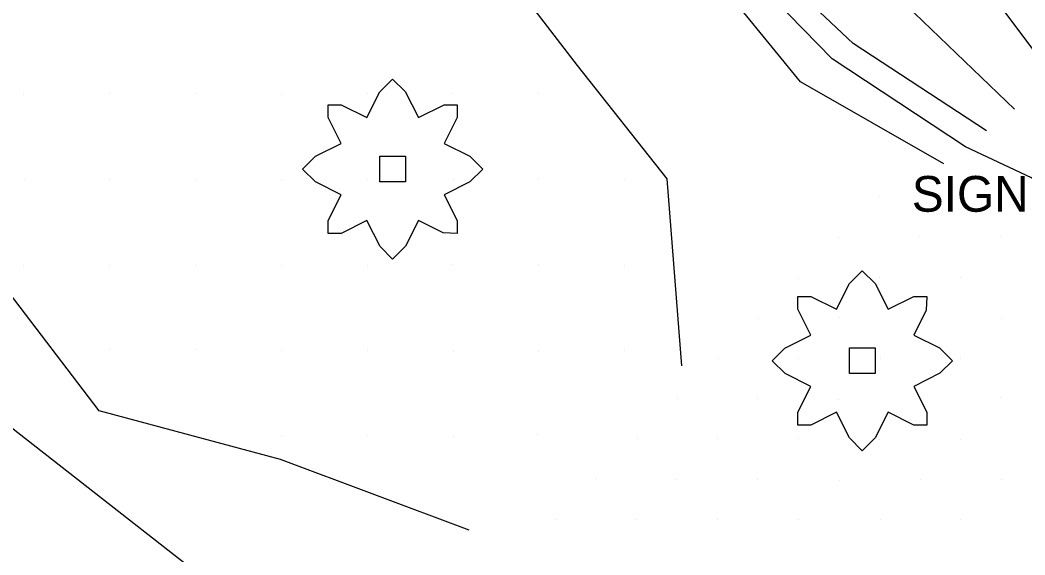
# Model space of a CAD drawing. Extents: x 1602514 to 1609837, y 863887 to 871157.
# Drawn here: x 1605247.7 to 1605423.3, y 867056.2 to 867149.8 of the extents above; entities that cross this region are included whole.
import ezdxf

# ---------------------------------------------------------------- set-up
doc = ezdxf.new("R2010")
doc.units = 0
for name, color, linetype in [('Environmental-New trees', 7, 'Continuous'), ('Roadway-Signs', 7, 'Continuous'), ('Survey-Ditches', 7, 'Continuous'), ('Survey-Entrances', 7, 'Continuous'), ('Survey-Flow line', 7, 'Continuous'), ('Survey-Ridge Lines', 7, 'Continuous'), ('Survey-Shoulders', 7, 'Continuous'), ('Survey-Spot dirt', 7, 'Continuous')]:
    doc.layers.add(name, color=color, linetype=linetype)

msp = doc.modelspace()

# ---------------------------------------------------------------- linework, layer by layer
at = {"layer": 'Environmental-New trees'}
for points in [[(1605301.57, 867134.94), (1605303.82, 867134.94), (1605308.32, 867132.69), (1605310.57, 867137.19), (1605312.82, 867139.44), (1605315.02, 867137.25), (1605317.32, 867132.69), (1605321.83, 867134.94), (1605324.08, 867134.94), (1605324.08, 867132.69), (1605321.83, 867128.19), (1605326.33, 867125.94), (1605328.58, 867123.69), (1605326.33, 867121.44), (1605321.83, 867119.19), (1605324.08, 867114.69), (1605324.08, 867112.44), (1605321.65, 867112.52), (1605317.32, 867114.69), (1605315.07, 867110.19), (1605312.82, 867107.94), (1605310.63, 867110.13), (1605308.32, 867114.69), (1605303.82, 867112.44), (1605301.57, 867112.44), (1605301.57, 867114.69), (1605303.82, 867119.19), (1605299.32, 867121.44), (1605297.07, 867123.69), (1605299.32, 867125.94), (1605303.82, 867128.19), (1605301.57, 867132.69)], [(1605301.57, 867134.94), (1605303.82, 867134.94), (1605308.32, 867132.69), (1605310.57, 867137.19), (1605312.82, 867139.44), (1605315.02, 867137.25), (1605317.32, 867132.69), (1605321.83, 867134.94), (1605324.08, 867134.94), (1605324.08, 867132.69), (1605321.83, 867128.19), (1605326.33, 867125.94), (1605328.58, 867123.69), (1605326.33, 867121.44), (1605321.83, 867119.19), (1605324.08, 867114.69), (1605324.08, 867112.44), (1605321.65, 867112.52), (1605317.32, 867114.69), (1605315.07, 867110.19), (1605312.82, 867107.94), (1605310.63, 867110.13), (1605308.32, 867114.69), (1605303.82, 867112.44), (1605301.57, 867112.44), (1605301.57, 867114.69), (1605303.82, 867119.19), (1605299.32, 867121.44), (1605297.07, 867123.69), (1605299.32, 867125.94), (1605303.82, 867128.19), (1605301.57, 867132.69)], [(1605315.07, 867125.94), (1605315.07, 867121.44), (1605310.57, 867121.44), (1605310.57, 867125.94)], [(1605315.07, 867125.94), (1605315.07, 867121.44), (1605310.57, 867121.44), (1605310.57, 867125.94)], [(1605383.66, 867078.91), (1605383.66, 867081.16), (1605385.91, 867085.66), (1605381.41, 867087.91), (1605379.16, 867090.16), (1605381.35, 867092.35), (1605385.91, 867094.66), (1605383.66, 867099.16), (1605383.66, 867101.41), (1605385.91, 867101.41), (1605390.41, 867099.16), (1605392.66, 867103.66), (1605394.91, 867105.91), (1605397.17, 867103.66), (1605399.42, 867099.16), (1605403.92, 867101.41), (1605406.17, 867101.41), (1605406.08, 867098.99), (1605403.92, 867094.66), (1605408.42, 867092.41), (1605410.67, 867090.16), (1605408.48, 867087.97), (1605403.92, 867085.66), (1605406.17, 867081.16), (1605406.17, 867078.91), (1605403.92, 867078.91), (1605399.42, 867081.16), (1605397.17, 867076.66), (1605394.91, 867074.41), (1605392.66, 867076.66), (1605390.41, 867081.16), (1605385.91, 867078.91)], [(1605383.66, 867078.91), (1605383.66, 867081.16), (1605385.91, 867085.66), (1605381.41, 867087.91), (1605379.16, 867090.16), (1605381.35, 867092.35), (1605385.91, 867094.66), (1605383.66, 867099.16), (1605383.66, 867101.41), (1605385.91, 867101.41), (1605390.41, 867099.16), (1605392.66, 867103.66), (1605394.91, 867105.91), (1605397.17, 867103.66), (1605399.42, 867099.16), (1605403.92, 867101.41), (1605406.17, 867101.41), (1605406.08, 867098.99), (1605403.92, 867094.66), (1605408.42, 867092.41), (1605410.67, 867090.16), (1605408.48, 867087.97), (1605403.92, 867085.66), (1605406.17, 867081.16), (1605406.17, 867078.91), (1605403.92, 867078.91), (1605399.42, 867081.16), (1605397.17, 867076.66), (1605394.91, 867074.41), (1605392.66, 867076.66), (1605390.41, 867081.16), (1605385.91, 867078.91)], [(1605392.66, 867092.41), (1605397.17, 867092.41), (1605397.17, 867087.91), (1605392.66, 867087.91)], [(1605392.66, 867092.41), (1605397.17, 867092.41), (1605397.17, 867087.91), (1605392.66, 867087.91)]]:
    msp.add_lwpolyline(points, close=True, dxfattribs=at)
at = {"layer": 'Survey-Ditches'}
for points in [[(1605416.61, 867130.37), (1605393.32, 867145.64), (1605374.76, 867163.22), (1605359.95, 867184.15), (1605345.35, 867204.25), (1605329.25, 867223.78), (1605314.17, 867243), (1605299.43, 867263.93), (1605283.11, 867283.13), (1605268.84, 867303.43)], [(1605416.61, 867130.37), (1605393.32, 867145.64), (1605374.76, 867163.22), (1605359.95, 867184.15), (1605345.35, 867204.25), (1605329.25, 867223.78), (1605314.17, 867243), (1605299.43, 867263.93), (1605283.11, 867283.13), (1605268.84, 867303.43)], [(1605409.15, 867124.61), (1605384.1, 867138.94), (1605368.19, 867158.48), (1605352.34, 867178.8), (1605336.73, 867198.14), (1605321.53, 867218.37), (1605305.96, 867237.11), (1605290.54, 867257.69), (1605275.15, 867277.56), (1605260.57, 867297.61)], [(1605409.15, 867124.61), (1605384.1, 867138.94), (1605368.19, 867158.48), (1605352.34, 867178.8), (1605336.73, 867198.14), (1605321.53, 867218.37), (1605305.96, 867237.11), (1605290.54, 867257.69), (1605275.15, 867277.56), (1605260.57, 867297.61)]]:
    msp.add_lwpolyline(points, dxfattribs=at)
at = {"layer": 'Survey-Entrances'}
msp.add_lwpolyline([(1605291.69, 867042.8), (1605245.98, 867078.59), (1605219.04, 867104.4), (1605203.54, 867111.71), (1605201.31, 867118.34)], dxfattribs=at)
msp.add_lwpolyline([(1605291.69, 867042.8), (1605245.98, 867078.59), (1605219.04, 867104.4), (1605203.54, 867111.71), (1605201.31, 867118.34)], dxfattribs=at)
at = {"layer": 'Survey-Flow line'}
msp.add_lwpolyline([(1605483.22, 867053.97), (1605467.96, 867073.75), (1605453.46, 867094.06), (1605436.46, 867112.84), (1605424.5, 867122.15), (1605412.97, 867127.56), (1605389.62, 867142.95), (1605371.95, 867161.19), (1605355.8, 867181.23), (1605340.93, 867201.11), (1605325.15, 867220.9), (1605309.26, 867239.48), (1605293.81, 867259.99), (1605279.34, 867280.49), (1605264.59, 867300.44), (1605249.31, 867320.37), (1605233.7, 867339.71), (1605216.94, 867358.74), (1605199.93, 867377.13), (1605181.39, 867394.89), (1605157.18, 867409.78), (1605132.49, 867419.31)], dxfattribs=at)
msp.add_lwpolyline([(1605483.22, 867053.97), (1605467.96, 867073.75), (1605453.46, 867094.06), (1605436.46, 867112.84), (1605424.5, 867122.15), (1605412.97, 867127.56), (1605389.62, 867142.95), (1605371.95, 867161.19), (1605355.8, 867181.23), (1605340.93, 867201.11), (1605325.15, 867220.9), (1605309.26, 867239.48), (1605293.81, 867259.99), (1605279.34, 867280.49), (1605264.59, 867300.44), (1605249.31, 867320.37), (1605233.7, 867339.71), (1605216.94, 867358.74), (1605199.93, 867377.13), (1605181.39, 867394.89), (1605157.18, 867409.78), (1605132.49, 867419.31)], dxfattribs=at)
at = {"layer": 'Survey-Ridge Lines'}
for points in [[(1605421.54, 867134.17), (1605402.61, 867152.39), (1605384.02, 867169.92), (1605368.46, 867190.14), (1605352.04, 867208.98), (1605338.24, 867230.08), (1605323.5, 867249.7), (1605308.77, 867270.48), (1605294.12, 867290.82), (1605278.71, 867310.38), (1605261.54, 867328.96), (1605246.28, 867348.6), (1605232.36, 867369.55), (1605214.75, 867387.58), (1605193.21, 867403.18), (1605171.5, 867419.55), (1605149.94, 867432.04)], [(1605421.54, 867134.17), (1605402.61, 867152.39), (1605384.02, 867169.92), (1605368.46, 867190.14), (1605352.04, 867208.98), (1605338.24, 867230.08), (1605323.5, 867249.7), (1605308.77, 867270.48), (1605294.12, 867290.82), (1605278.71, 867310.38), (1605261.54, 867328.96), (1605246.28, 867348.6), (1605232.36, 867369.55), (1605214.75, 867387.58), (1605193.21, 867403.18), (1605171.5, 867419.55), (1605149.94, 867432.04)], [(1605363.38, 867089.27), (1605360.79, 867121.99), (1605345.12, 867141.8), (1605329.24, 867162.54), (1605313.94, 867181.99), (1605301.03, 867203.98), (1605286.15, 867222.89), (1605273.65, 867245.84)], [(1605363.38, 867089.27), (1605360.79, 867121.99), (1605345.12, 867141.8), (1605329.24, 867162.54), (1605313.94, 867181.99), (1605301.03, 867203.98), (1605286.15, 867222.89), (1605273.65, 867245.84)], [(1605326.18, 867060.55), (1605293.21, 867072.86), (1605261.54, 867081.39), (1605244.92, 867103.2), (1605229.41, 867122.1)], [(1605326.18, 867060.55), (1605293.21, 867072.86), (1605261.54, 867081.39), (1605244.92, 867103.2), (1605229.41, 867122.1)]]:
    msp.add_lwpolyline(points, dxfattribs=at)
at = {"layer": 'Survey-Shoulders'}
msp.add_lwpolyline([(1605506.7, 867040.7), (1605491.11, 867060.25), (1605475.52, 867079.81), (1605459.53, 867099.03), (1605444.21, 867118.81), (1605429.13, 867138.8), (1605410.83, 867163.21), (1605396.18, 867183.47), (1605381.57, 867203.75), (1605367.12, 867224.15), (1605352.77, 867244.61), (1605338.38, 867265.05), (1605323.96, 867285.47), (1605309.51, 867305.87), (1605295.12, 867326.31), (1605280.77, 867346.77), (1605266.35, 867367.19), (1605251.99, 867387.66), (1605237.14, 867408.73), (1605221.74, 867428.49), (1605206.68, 867448.47), (1605188.4, 867466.27)], dxfattribs=at)
msp.add_lwpolyline([(1605506.7, 867040.7), (1605491.11, 867060.25), (1605475.52, 867079.81), (1605459.53, 867099.03), (1605444.21, 867118.81), (1605429.13, 867138.8), (1605410.83, 867163.21), (1605396.18, 867183.47), (1605381.57, 867203.75), (1605367.12, 867224.15), (1605352.77, 867244.61), (1605338.38, 867265.05), (1605323.96, 867285.47), (1605309.51, 867305.87), (1605295.12, 867326.31), (1605280.77, 867346.77), (1605266.35, 867367.19), (1605251.99, 867387.66), (1605237.14, 867408.73), (1605221.74, 867428.49), (1605206.68, 867448.47), (1605188.4, 867466.27)], dxfattribs=at)
at = {"layer": 'Survey-Spot dirt'}
for p, q in [((1605263.41, 867136.97), (1605263.41, 867136.97)), ((1605263.41, 867136.97), (1605263.41, 867136.97)), ((1605308.46, 867136.97), (1605308.46, 867136.97)), ((1605308.46, 867136.97), (1605308.46, 867136.97)), ((1605248.32, 867136.7), (1605248.32, 867136.7)), ((1605248.32, 867136.7), (1605248.32, 867136.7)), ((1605278.5, 867136.89), (1605278.5, 867136.89)), ((1605278.5, 867136.89), (1605278.5, 867136.89)), ((1605293.34, 867136.79), (1605293.34, 867136.79)), ((1605293.34, 867136.79), (1605293.34, 867136.79)), ((1605323.36, 867136.86), (1605323.36, 867136.86)), ((1605323.36, 867136.86), (1605323.36, 867136.86)), ((1605338.4, 867136.93), (1605338.4, 867136.93)), ((1605338.4, 867136.93), (1605338.4, 867136.93)), ((1605248.45, 867121.84), (1605248.45, 867121.84)), ((1605248.45, 867121.84), (1605248.45, 867121.84)), ((1605263.37, 867121.83), (1605263.37, 867121.83)), ((1605263.37, 867121.83), (1605263.37, 867121.83)), ((1605278.38, 867121.71), (1605278.38, 867121.71)), ((1605278.38, 867121.71), (1605278.38, 867121.71)), ((1605293.34, 867121.91), (1605293.34, 867121.91)), ((1605293.34, 867121.91), (1605293.34, 867121.91)), ((1605308.43, 867121.81), (1605308.43, 867121.81)), ((1605308.43, 867121.81), (1605308.43, 867121.81)), ((1605323.48, 867121.86), (1605323.48, 867121.86)), ((1605323.48, 867121.86), (1605323.48, 867121.86)), ((1605338.29, 867122.02), (1605338.29, 867122.02)), ((1605338.29, 867122.02), (1605338.29, 867122.02)), ((1605353.33, 867121.86), (1605353.33, 867121.86)), ((1605353.33, 867121.86), (1605353.33, 867121.86)), ((1605397.94, 867118.93), (1605397.94, 867118.93)), ((1605397.94, 867118.93), (1605397.94, 867118.93)), ((1605390.76, 867111.78), (1605390.76, 867111.78)), ((1605390.76, 867111.78), (1605390.76, 867111.78)), ((1605404.93, 867111.84), (1605404.93, 867111.84)), ((1605404.93, 867111.84), (1605404.93, 867111.84)), ((1605419.04, 867111.84), (1605419.04, 867111.84)), ((1605419.04, 867111.84), (1605419.04, 867111.84)), ((1605248.34, 867106.82), (1605248.34, 867106.82)), ((1605248.34, 867106.82), (1605248.34, 867106.82)), ((1605263.41, 867106.74), (1605263.41, 867106.74)), ((1605263.41, 867106.74), (1605263.41, 867106.74)), ((1605278.44, 867106.85), (1605278.44, 867106.85)), ((1605278.44, 867106.85), (1605278.44, 867106.85)), ((1605293.35, 867106.77), (1605293.35, 867106.77)), ((1605293.35, 867106.77), (1605293.35, 867106.77)), ((1605308.39, 867106.82), (1605308.39, 867106.82)), ((1605308.39, 867106.82), (1605308.39, 867106.82)), ((1605323.32, 867107.03), (1605323.32, 867107.03)), ((1605323.32, 867107.03), (1605323.32, 867107.03)), ((1605338.34, 867107.04), (1605338.34, 867107.04)), ((1605338.34, 867107.04), (1605338.34, 867107.04)), ((1605353.39, 867106.84), (1605353.39, 867106.84)), ((1605353.39, 867106.84), (1605353.39, 867106.84)), ((1605383.74, 867104.62), (1605383.74, 867104.62)), ((1605383.74, 867104.62), (1605383.74, 867104.62)), ((1605397.97, 867104.7), (1605397.97, 867104.7)), ((1605397.97, 867104.7), (1605397.97, 867104.7)), ((1605412.1, 867104.66), (1605412.1, 867104.66)), ((1605412.1, 867104.66), (1605412.1, 867104.66)), ((1605376.8, 867097.63), (1605376.8, 867097.63)), ((1605376.8, 867097.63), (1605376.8, 867097.63)), ((1605390.85, 867097.65), (1605390.85, 867097.65)), ((1605390.85, 867097.65), (1605390.85, 867097.65)), ((1605405.1, 867097.62), (1605405.1, 867097.62)), ((1605405.1, 867097.62), (1605405.1, 867097.62)), ((1605419.17, 867097.6), (1605419.17, 867097.6)), ((1605419.17, 867097.6), (1605419.17, 867097.6)), ((1605263.32, 867092.09), (1605263.32, 867092.09)), ((1605263.32, 867092.09), (1605263.32, 867092.09)), ((1605278.58, 867092.12), (1605278.58, 867092.12)), ((1605278.58, 867092.12), (1605278.58, 867092.12)), ((1605293.43, 867091.94), (1605293.43, 867091.94)), ((1605293.43, 867091.94), (1605293.43, 867091.94)), ((1605308.5, 867091.9), (1605308.5, 867091.9)), ((1605308.5, 867091.9), (1605308.5, 867091.9)), ((1605323.49, 867091.78), (1605323.49, 867091.78)), ((1605323.49, 867091.78), (1605323.49, 867091.78)), ((1605338.39, 867091.86), (1605338.39, 867091.86)), ((1605338.39, 867091.86), (1605338.39, 867091.86)), ((1605353.29, 867091.98), (1605353.29, 867091.98)), ((1605353.29, 867091.98), (1605353.29, 867091.98)), ((1605369.74, 867090.53), (1605369.74, 867090.53)), ((1605369.74, 867090.53), (1605369.74, 867090.53)), ((1605383.82, 867090.56), (1605383.82, 867090.56)), ((1605383.82, 867090.56), (1605383.82, 867090.56)), ((1605398.04, 867090.51), (1605398.04, 867090.51)), ((1605398.04, 867090.51), (1605398.04, 867090.51)), ((1605412.07, 867090.5), (1605412.07, 867090.5)), ((1605412.07, 867090.5), (1605412.07, 867090.5)), ((1605362.55, 867083.59), (1605362.55, 867083.59)), ((1605362.55, 867083.59), (1605362.55, 867083.59)), ((1605376.64, 867083.56), (1605376.64, 867083.56)), ((1605376.64, 867083.56), (1605376.64, 867083.56)), ((1605390.81, 867083.42), (1605390.81, 867083.42)), ((1605390.81, 867083.42), (1605390.81, 867083.42)), ((1605405.04, 867083.52), (1605405.04, 867083.52)), ((1605405.04, 867083.52), (1605405.04, 867083.52)), ((1605419.14, 867083.65), (1605419.14, 867083.65)), ((1605419.14, 867083.65), (1605419.14, 867083.65)), ((1605293.35, 867077.06), (1605293.35, 867077.06)), ((1605293.35, 867077.06), (1605293.35, 867077.06)), ((1605308.51, 867077.09), (1605308.51, 867077.09)), ((1605308.51, 867077.09), (1605308.51, 867077.09)), ((1605323.4, 867076.94), (1605323.4, 867076.94)), ((1605323.4, 867076.94), (1605323.4, 867076.94)), ((1605338.07, 867077.18), (1605338.07, 867077.18)), ((1605338.07, 867077.18), (1605338.07, 867077.18)), ((1605355.69, 867076.49), (1605355.69, 867076.49)), ((1605355.69, 867076.49), (1605355.69, 867076.49)), ((1605369.59, 867076.56), (1605369.59, 867076.56)), ((1605369.59, 867076.56), (1605369.59, 867076.56)), ((1605383.74, 867076.48), (1605383.74, 867076.48)), ((1605383.74, 867076.48), (1605383.74, 867076.48)), ((1605397.97, 867076.43), (1605397.97, 867076.43)), ((1605397.97, 867076.43), (1605397.97, 867076.43)), ((1605412.03, 867076.41), (1605412.03, 867076.41)), ((1605412.03, 867076.41), (1605412.03, 867076.41)), ((1605348.51, 867069.49), (1605348.51, 867069.49)), ((1605348.51, 867069.49), (1605348.51, 867069.49)), ((1605362.5, 867069.37), (1605362.5, 867069.37)), ((1605362.5, 867069.37), (1605362.5, 867069.37)), ((1605376.67, 867069.47), (1605376.67, 867069.47)), ((1605376.67, 867069.47), (1605376.67, 867069.47)), ((1605390.88, 867069.29), (1605390.88, 867069.29)), ((1605390.88, 867069.29), (1605390.88, 867069.29)), ((1605405.03, 867069.31), (1605405.03, 867069.31)), ((1605405.03, 867069.31), (1605405.03, 867069.31)), ((1605419.29, 867069.38), (1605419.29, 867069.38)), ((1605419.29, 867069.38), (1605419.29, 867069.38)), ((1605258.93, 867068.04), (1605258.93, 867068.04)), ((1605258.93, 867068.04), (1605258.93, 867068.04)), ((1605341.42, 867062.39), (1605341.42, 867062.39)), ((1605341.42, 867062.39), (1605341.42, 867062.39)), ((1605355.48, 867062.36), (1605355.48, 867062.36)), ((1605355.48, 867062.36), (1605355.48, 867062.36)), ((1605369.61, 867062.46), (1605369.61, 867062.46)), ((1605369.61, 867062.46), (1605369.61, 867062.46)), ((1605383.75, 867062.36), (1605383.75, 867062.36)), ((1605383.75, 867062.36), (1605383.75, 867062.36)), ((1605398.02, 867062.31), (1605398.02, 867062.31)), ((1605398.02, 867062.31), (1605398.02, 867062.31)), ((1605412.11, 867062.36), (1605412.11, 867062.36)), ((1605412.11, 867062.36), (1605412.11, 867062.36))]:
    msp.add_line(p, q, dxfattribs=at)

# ---------------------------------------------------------------- texts
at = {"layer": 'Roadway-Signs'}
msp.add_text('SIGN', height=6.25, dxfattribs=at).set_placement((1605403.57, 867116.23))
msp.add_text('SIGN', height=6.25, dxfattribs=at).set_placement((1605403.57, 867116.23))

doc.saveas('drawing.dxf')
